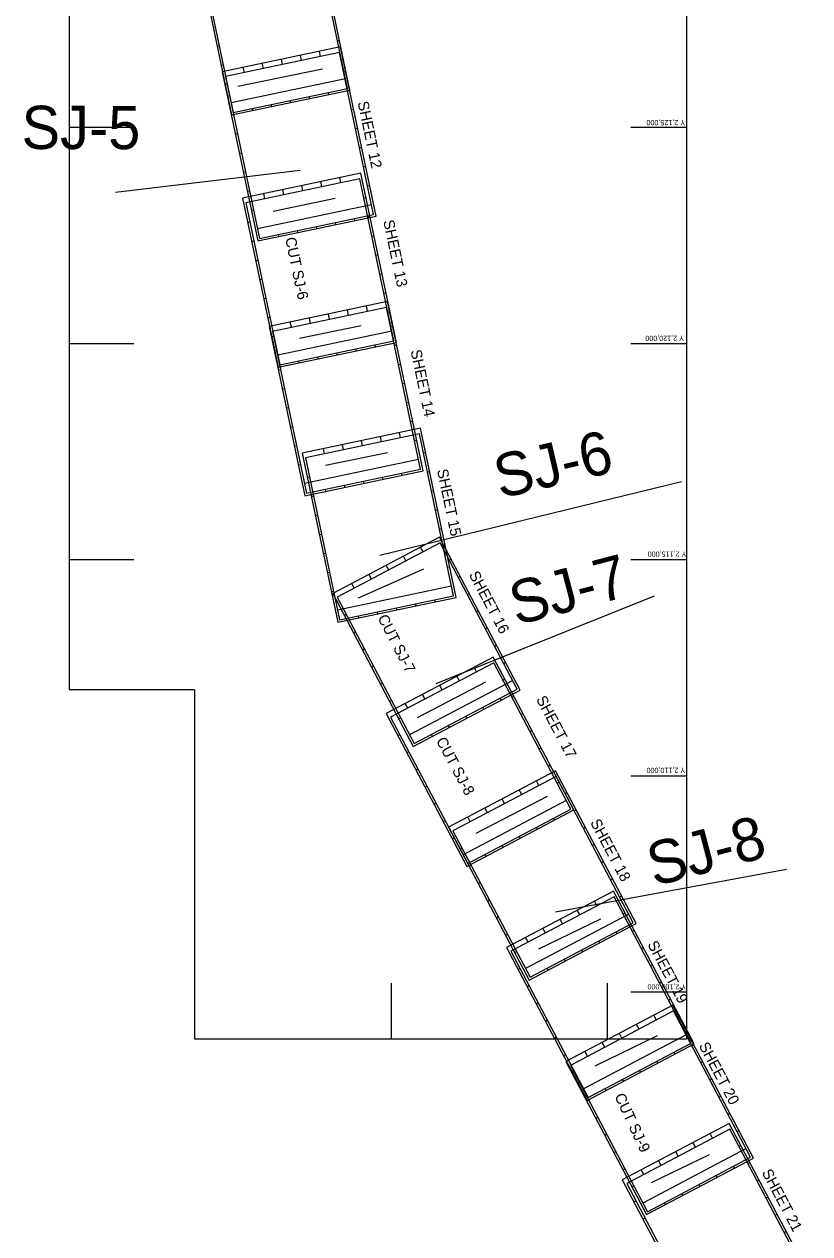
# Model space of a CAD drawing. Extents: x 518852 to 589310, y 1937169 to 2155394.
# Drawn here: x 522724 to 540912, y 2099579 to 2127557 of the extents above; entities that cross this region are included whole.
import ezdxf

# ---------------------------------------------------------------- set-up
doc = ezdxf.new("R2010")
doc.units = 0
for name, color, linetype in [('Level 1', 7, 'Continuous'), ('Level 2', 7, 'Continuous'), ('Level 3', 7, 'Continuous'), ('Level 58', 7, 'Continuous'), ('Level 63', 7, 'Continuous')]:
    doc.layers.add(name, color=color, linetype=linetype)

msp = doc.modelspace()

# ---------------------------------------------------------------- linework, layer by layer
at = {"layer": 'Level 1'}
for p, q in [((527098, 2127490), (527147, 2127500)), ((527191, 2127049), (527240, 2127060)), ((529584, 2126810), (529558, 2126932)), ((529974, 2127174), (530023, 2127185)), ((528263, 2126532), (528237, 2126654)), ((528703, 2126625), (528678, 2126747)), ((529144, 2126717), (529118, 2126839)), ((530067, 2126734), (530116, 2126744)), ((527283, 2126609), (527332, 2126619)), ((527823, 2126440), (527797, 2126562)), ((530117, 2126462), (530166, 2126472)), ((527376, 2126169), (527425, 2126179)), ((530159, 2126294), (527517, 2125738)), ((527426, 2125896), (527475, 2125907)), ((528895, 2125747), (528885, 2125796)), ((529335, 2125839), (529325, 2125888)), ((529776, 2125932), (529765, 2125981)), ((530210, 2126021), (530259, 2126032)), ((528014, 2125562), (528004, 2125611)), ((528454, 2125654), (528444, 2125703)), ((530302, 2125581), (530351, 2125591)), ((527518, 2125456), (527567, 2125466)), ((527611, 2125016), (527660, 2125026)), ((530395, 2125141), (530444, 2125151)), ((530487, 2124700), (530536, 2124710)), ((527703, 2124575), (527752, 2124585)), ((527796, 2124135), (527845, 2124145)), ((530580, 2124260), (530629, 2124270)), ((529617, 2123795), (529591, 2123917)), ((530057, 2123887), (530031, 2124010)), ((527888, 2123694), (527937, 2123705)), ((528295, 2123517), (528270, 2123639)), ((528736, 2123610), (528710, 2123732)), ((529176, 2123702), (529150, 2123825)), ((530672, 2123819), (530721, 2123830)), ((530765, 2123379), (528122, 2122824)), ((530590, 2123539), (530639, 2123550)), ((527981, 2123254), (528030, 2123264)), ((530381, 2123017), (530371, 2123066)), ((530682, 2123099), (530731, 2123109)), ((527899, 2122974), (527947, 2122984)), ((529060, 2122740), (529049, 2122789)), ((529500, 2122832), (529490, 2122881)), ((529940, 2122925), (529930, 2122974)), ((527991, 2122534), (528040, 2122544)), ((528619, 2122647), (528609, 2122696)), ((530775, 2122659), (530824, 2122669)), ((530867, 2122218), (530916, 2122228)), ((528084, 2122093), (528132, 2122103)), ((528176, 2121653), (528225, 2121663)), ((530960, 2121778), (531009, 2121788)), ((531052, 2121337), (531101, 2121348)), ((528269, 2121212), (528318, 2121223)), ((528361, 2120772), (528410, 2120782)), ((529351, 2120638), (529326, 2120760)), ((529792, 2120731), (529766, 2120853)), ((530232, 2120823), (530206, 2120945)), ((530672, 2120916), (530647, 2121038)), ((531145, 2120897), (531194, 2120907)), ((528911, 2120546), (528885, 2120668)), ((531205, 2120568), (531254, 2120578)), ((528454, 2120332), (528503, 2120342)), ((531237, 2120457), (528595, 2119902)), ((528514, 2120002), (528563, 2120013)), ((529973, 2119910), (529962, 2119959)), ((530413, 2120002), (530403, 2120051)), ((530854, 2120095), (530843, 2120144)), ((531298, 2120127), (531347, 2120138)), ((529092, 2119725), (529082, 2119774)), ((529532, 2119817), (529522, 2119866)), ((531390, 2119687), (531439, 2119697)), ((528607, 2119562), (528655, 2119572)), ((528699, 2119122), (528748, 2119132)), ((531483, 2119247), (531532, 2119257)), ((531575, 2118806), (531624, 2118816)), ((528792, 2118681), (528840, 2118691)), ((528884, 2118241), (528933, 2118251)), ((531668, 2118366), (531717, 2118376)), ((530998, 2117897), (530972, 2118019)), ((531438, 2117989), (531413, 2118112)), ((528977, 2117800), (529025, 2117811)), ((529677, 2117619), (529651, 2117742)), ((530117, 2117712), (530091, 2117834)), ((530558, 2117804), (530532, 2117927)), ((531760, 2117925), (531809, 2117936)), ((531853, 2117485), (529211, 2116930)), ((531971, 2117642), (532020, 2117652)), ((529069, 2117360), (529118, 2117370)), ((531469, 2117123), (531459, 2117172)), ((532064, 2117201), (532113, 2117212)), ((529280, 2117076), (529329, 2117087)), ((530148, 2116846), (530138, 2116895)), ((530588, 2116938), (530578, 2116987)), ((531029, 2117031), (531018, 2117080)), ((529372, 2116636), (529421, 2116646)), ((529707, 2116753), (529697, 2116802)), ((532156, 2116761), (532205, 2116771)), ((532249, 2116320), (532298, 2116331)), ((529465, 2116195), (529514, 2116206)), ((529558, 2115755), (529606, 2115765)), ((532341, 2115880), (532390, 2115890)), ((531958, 2115352), (531900, 2115462)), ((532434, 2115440), (532483, 2115450)), ((529650, 2115315), (529699, 2115325)), ((531560, 2115142), (531502, 2115253)), ((532566, 2115164), (532611, 2115187)), ((529743, 2114874), (529791, 2114885)), ((531162, 2114932), (531104, 2115043)), ((532526, 2114999), (532575, 2115010)), ((530366, 2114512), (530308, 2114623)), ((530764, 2114722), (530706, 2114833)), ((532776, 2114766), (532820, 2114789)), ((529835, 2114434), (529884, 2114444)), ((532619, 2114559), (529976, 2114004)), ((532986, 2114368), (533030, 2114391)), ((531354, 2114012), (531344, 2114061)), ((531795, 2114105), (531784, 2114154)), ((532235, 2114197), (532225, 2114246)), ((530134, 2113881), (530178, 2113904)), ((530473, 2113827), (530463, 2113876)), ((530914, 2113920), (530904, 2113969)), ((533196, 2113970), (533240, 2113993)), ((530344, 2113483), (530388, 2113506)), ((533406, 2113571), (533450, 2113595)), ((530554, 2113085), (530598, 2113108)), ((533616, 2113173), (533660, 2113197)), ((530763, 2112687), (530808, 2112710)), ((533197, 2112577), (533139, 2112687)), ((533826, 2112775), (533870, 2112799)), ((534036, 2112377), (531647, 2111118)), ((532799, 2112367), (532741, 2112477)), ((533805, 2112388), (533849, 2112412)), ((526664, 2112160), (523767, 2112160)), ((526664, 2112160), (526664, 2104085)), ((530973, 2112289), (531018, 2112312)), ((532401, 2112157), (532343, 2112267)), ((531183, 2111891), (531227, 2111914)), ((531605, 2111737), (531546, 2111848)), ((532003, 2111947), (531945, 2112058)), ((533766, 2111924), (533742, 2111968)), ((534015, 2111990), (534059, 2112014)), ((532970, 2111504), (532946, 2111549)), ((533368, 2111714), (533344, 2111758)), ((534225, 2111592), (534269, 2111616)), ((531393, 2111493), (531437, 2111516)), ((532572, 2111295), (532548, 2111339)), ((531372, 2111106), (531417, 2111129)), ((532173, 2111085), (532150, 2111129)), ((534435, 2111194), (534479, 2111218)), ((531582, 2110708), (531626, 2110731)), ((534644, 2110796), (534689, 2110820)), ((534854, 2110398), (534899, 2110421)), ((531792, 2110310), (531836, 2110333)), ((532002, 2109912), (532046, 2109935)), ((534243, 2109738), (534185, 2109848)), ((534641, 2109948), (534583, 2110058)), ((535064, 2110000), (535108, 2110023)), ((535274, 2109602), (532886, 2108343)), ((533845, 2109528), (533787, 2109639)), ((535249, 2109760), (535294, 2109783)), ((532212, 2109514), (532256, 2109537)), ((533447, 2109318), (533389, 2109429)), ((535459, 2109361), (535503, 2109385)), ((532422, 2109116), (532466, 2109139)), ((533049, 2109108), (532991, 2109219)), ((535004, 2109149), (534981, 2109193)), ((532632, 2108718), (532676, 2108741)), ((534208, 2108729), (534185, 2108773)), ((534606, 2108939), (534583, 2108983)), ((535669, 2108963), (535713, 2108987)), ((532817, 2108477), (532861, 2108500)), ((533810, 2108519), (533787, 2108564)), ((535879, 2108565), (535923, 2108589)), ((533412, 2108309), (533389, 2108354)), ((536089, 2108167), (536133, 2108191)), ((533027, 2108079), (533071, 2108102)), ((533237, 2107681), (533281, 2107704)), ((536299, 2107769), (536343, 2107793)), ((536509, 2107371), (536553, 2107395)), ((533446, 2107283), (533491, 2107306)), ((535586, 2106955), (535527, 2107065)), ((535984, 2107165), (535925, 2107275)), ((533656, 2106885), (533700, 2106908)), ((536718, 2106973), (534330, 2105714)), ((535188, 2106745), (535129, 2106856)), ((536592, 2106977), (536636, 2107000)), ((533866, 2106487), (533910, 2106510)), ((534790, 2106535), (534731, 2106646)), ((536449, 2106520), (536425, 2106564)), ((536802, 2106578), (536846, 2106602)), ((534392, 2106325), (534333, 2106436)), ((536051, 2106310), (536027, 2106354)), ((534076, 2106089), (534120, 2106112)), ((535255, 2105890), (535231, 2105935)), ((535653, 2106100), (535629, 2106144)), ((537011, 2106180), (537056, 2106204)), ((534159, 2105694), (534203, 2105717)), ((534856, 2105680), (534833, 2105725)), ((537221, 2105782), (537266, 2105806)), ((537431, 2105384), (537475, 2105408)), ((534369, 2105296), (534413, 2105319)), ((534579, 2104898), (534623, 2104921)), ((537641, 2104986), (537685, 2105010)), ((537359, 2104523), (537300, 2104634)), ((537851, 2104588), (537895, 2104611)), ((534789, 2104500), (534833, 2104523)), ((536961, 2104313), (536902, 2104424)), ((537967, 2104335), (538011, 2104358)), ((534999, 2104102), (535043, 2104125)), ((538061, 2104190), (535673, 2102931)), ((536165, 2103894), (536106, 2104004)), ((536563, 2104103), (536504, 2104214)), ((535209, 2103704), (535253, 2103727)), ((535767, 2103684), (535708, 2103794)), ((537791, 2103737), (537768, 2103781)), ((538177, 2103937), (538221, 2103960)), ((537393, 2103527), (537370, 2103571)), ((538386, 2103539), (538431, 2103562)), ((535418, 2103306), (535463, 2103329)), ((536597, 2103107), (536574, 2103152)), ((536995, 2103317), (536972, 2103361)), ((538596, 2103141), (538641, 2103164)), ((535534, 2103052), (535578, 2103076)), ((536199, 2102897), (536176, 2102942)), ((535744, 2102654), (535788, 2102678)), ((538806, 2102743), (538850, 2102766)), ((539016, 2102345), (539060, 2102368)), ((535954, 2102256), (535998, 2102280)), ((536164, 2101858), (536208, 2101882)), ((538662, 2101790), (538604, 2101901)), ((539226, 2101947), (539270, 2101970)), ((536374, 2101460), (536418, 2101483)), ((539436, 2101549), (537048, 2100289)), ((537866, 2101370), (537808, 2101481)), ((538264, 2101580), (538206, 2101691)), ((539270, 2101602), (539314, 2101625)), ((537468, 2101160), (537410, 2101271)), ((539480, 2101204), (539524, 2101227)), ((536584, 2101062), (536628, 2101085)), ((537070, 2100951), (537011, 2101061)), ((538768, 2100886), (538745, 2100930)), ((539166, 2101095), (539143, 2101140)), ((536793, 2100664), (536838, 2100687)), ((538370, 2100676), (538347, 2100720)), ((539690, 2100806), (539734, 2100829)), ((536837, 2100319), (536882, 2100343)), ((537972, 2100466), (537949, 2100510)), ((539900, 2100408), (539944, 2100431)), ((537574, 2100256), (537551, 2100300)), ((537047, 2099921), (537091, 2099945)), ((540109, 2100010), (540154, 2100033)), ((540319, 2099612), (540364, 2099635))]:
    msp.add_line(p, q, dxfattribs=at)
for points in [[(523767, 2141334), (523767, 2112160)], [(538065, 2104085), (538065, 2141334)], [(526664, 2104085), (538065, 2104085)]]:
    msp.add_lwpolyline(points, dxfattribs=at)
for points in [[(526702, 2129374), (527525, 2125459), (530265, 2126035), (529443, 2129949)], [(526777, 2129262), (527563, 2125518), (530206, 2126073), (529419, 2129817)], [(527308, 2126459), (528130, 2122545), (530870, 2123120), (530048, 2127035)], [(527382, 2126347), (528169, 2122604), (530811, 2123159), (530025, 2126902)], [(527780, 2123537), (528603, 2119622), (531343, 2120198), (530521, 2124112)], [(527855, 2123425), (528641, 2119681), (531284, 2120236), (530497, 2123980)], [(528396, 2120565), (529218, 2116650), (531958, 2117226), (531136, 2121141)], [(528470, 2120453), (529257, 2116710), (531899, 2117265), (531113, 2121008)], [(529162, 2117639), (529984, 2113724), (532724, 2114300), (531902, 2118215)], [(529236, 2117527), (530023, 2113784), (532665, 2114339), (531879, 2118082)], [(529866, 2114390), (531731, 2110851), (534208, 2112157), (532342, 2115696)], [(529968, 2114302), (531752, 2110919), (534140, 2112178), (532356, 2115562)], [(531104, 2111614), (532970, 2108076), (535447, 2109382), (533581, 2112920)], [(531207, 2111527), (532991, 2108144), (535379, 2109403), (533595, 2112787)], [(532549, 2108986), (534414, 2105447), (536891, 2106753), (535025, 2110291)], [(532651, 2108898), (534435, 2105515), (536823, 2106774), (535039, 2110158)], [(533891, 2106203), (535757, 2102664), (538233, 2103970), (536368, 2107508)], [(533993, 2106115), (535777, 2102732), (538166, 2103991), (536382, 2107375)], [(535266, 2103561), (537132, 2100023), (539608, 2101329), (537743, 2104867)], [(535368, 2103474), (537152, 2100090), (539541, 2101350), (537757, 2104733)], [(536569, 2100828), (538435, 2097290), (540912, 2098596), (539046, 2102134)], [(536672, 2100741), (538456, 2097357), (540844, 2098616), (539060, 2102000)]]:
    msp.add_lwpolyline(points, close=True, dxfattribs=at)
at = {"layer": 'Level 2'}
for p, q in [((523767, 2125174), (525259, 2125174)), ((536765, 2125174), (538065, 2125174)), ((523767, 2120174), (525259, 2120174)), ((536765, 2120174), (538065, 2120174)), ((523767, 2115174), (525259, 2115174)), ((536765, 2115174), (538065, 2115174)), ((536765, 2110174), (538065, 2110174)), ((531231, 2104085), (531231, 2105374)), ((536231, 2104085), (536231, 2105374)), ((536765, 2105174), (538065, 2105174))]:
    msp.add_line(p, q, dxfattribs=at)
at = {"layer": 'Level 58'}
for p, q in [((527672, 2126121), (529630, 2126526)), ((528487, 2123233), (529921, 2123530)), ((529094, 2120295), (530529, 2120592)), ((529702, 2117357), (531137, 2117654)), ((530461, 2114292), (531979, 2114961)), ((531832, 2111520), (533408, 2112343)), ((533184, 2108842), (534836, 2109705)), ((534635, 2106167), (536076, 2106865)), ((535942, 2103467), (537383, 2104164)), ((537248, 2100766), (538589, 2101415))]:
    msp.add_line(p, q, dxfattribs=at)
at = {"layer": 'Level 63'}
for p, q in [((524837, 2123675), (529115, 2124178)), ((530956, 2115279), (537942, 2116982)), ((532264, 2112310), (537313, 2114332)), ((535025, 2107023), (540370, 2108013))]:
    msp.add_line(p, q, dxfattribs=at)

# ---------------------------------------------------------------- texts
at = {"layer": 'Level 3'}
for s, p in [('Y 2,125,000', (538024, 2125340)), ('Y 2,120,000', (537996, 2120350)), ('Y 2,115,000', (538052, 2115360)), ('Y 2,110,000', (538025, 2110358)), ('Y 2,105,000', (538048, 2105352))]:
    msp.add_text(s, height=120, rotation=180, dxfattribs=at).set_placement(p)
at = {"layer": 'Level 58'}
for s, rotation, p in [('SHEET 12', 281.8635, (530443, 2125749)), ('SHEET 13', 281.8635, (531036, 2123005)), ('CUT SJ-6', 281.8635, (528764, 2122604)), ('SHEET 14', 281.8635, (531668, 2120004)), ('SHEET 15', 281.8635, (532280, 2117244)), ('SHEET 16', 297.789, (533012, 2114828)), ('CUT SJ-7', 297.3627, (530899, 2113826)), ('SHEET 17', 297.789, (534569, 2111945)), ('CUT SJ-8', 298.1725, (532252, 2110986)), ('SHEET 18', 297.789, (535822, 2109096)), ('SHEET 19', 297.789, (537146, 2106278)), ('SHEET 20', 297.789, (538335, 2103933)), ('CUT SJ-9', 295.0216, (536383, 2102763)), ('SHEET 21', 297.789, (539793, 2101000))]:
    msp.add_text(s, height=250, rotation=rotation, dxfattribs=at).set_placement(p)
at = {"layer": 'Level 63'}
for s, rotation, p in [('SJ-5', 359.891, (522663, 2124672)), ('SJ-6', 13.1571, (533738, 2116582)), ('SJ-7', 14.6568, (534116, 2113649)), ('SJ-8 ', 14.6568, (537302, 2107610))]:
    msp.add_text(s, height=1000, rotation=rotation, dxfattribs=at).set_placement(p)

doc.saveas('drawing.dxf')
